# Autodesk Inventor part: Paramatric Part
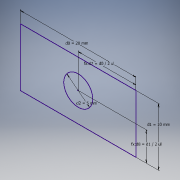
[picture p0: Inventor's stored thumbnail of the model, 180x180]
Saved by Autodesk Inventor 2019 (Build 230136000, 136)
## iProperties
Created: 2018-11
Part Number: Paramatric Part
Material: Generic
Document SubType Name: Modeling
Designer: Synergysoft
Density: 1 g/cm^3
Appearance: Default
Author: Synergysoft
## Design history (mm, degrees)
sketch "Sketch1"
  geometry: L1 (0, 0)-(20, 0); L2 (20, 0)-(20, 10); L3 (20, 10)-(0, 10); L4 (0, 10)-(0, 0); C1 r 2.5 at (10, 5)
  constraints: 8 end point, 2 parallel, 1 centre point, 1 horizontal, 1 perpendicular
  dimensions: "d0" = 20 distance of L3.end L2.end; "d1" = 10 distance of L2.end L1.end; "d2" = 5 diameter of C1; "d7" = 10 distance from line of C1.centre L2 (= 0.5 x d0); "d8" = 5 distance from line of L1 C1.centre (= 0.5 x d1)
